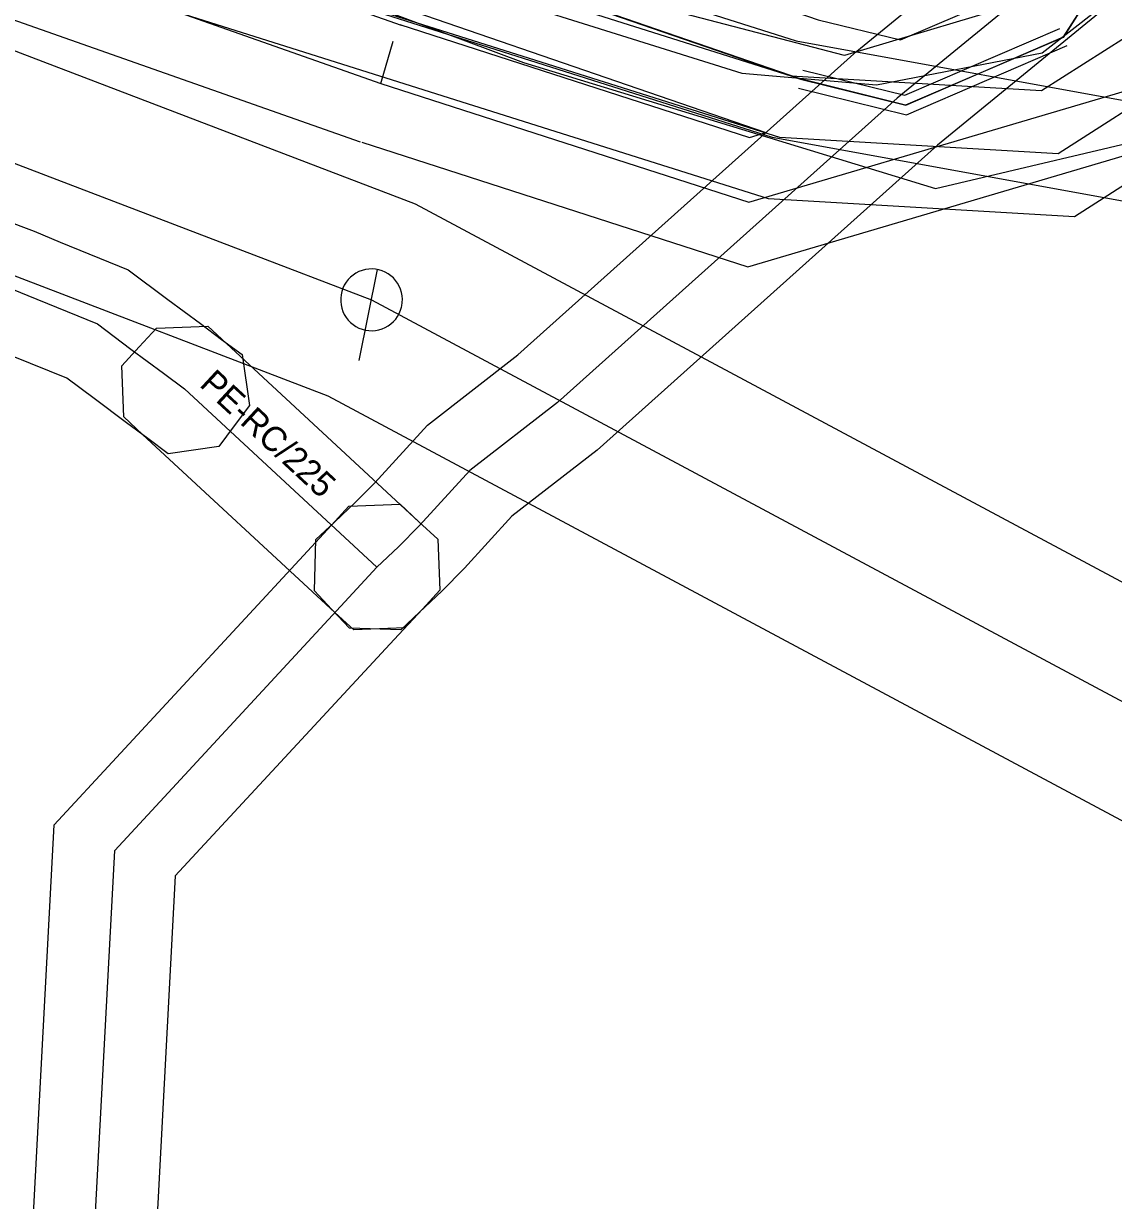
# Model space of a CAD drawing. Extents: x -762993 to -761845, y -975230 to -974501.
# Drawn here: x -762304.94 to -762287.32, y -975003.77 to -974984.74 of the extents above; entities that cross this region are included whole.
import ezdxf

# ---------------------------------------------------------------- set-up
doc = ezdxf.new("R2010")
doc.units = 0
for name, color, linetype in [('IS_CETIN_chranicka', 7, 'Continuous'), ('IS_CETIN_OP', 7, 'Continuous'), ('IS_CETIN_podzem optika zam', 7, 'Continuous'), ('IS_CETIN_podzem out of order', 7, 'Continuous'), ('IS_CEZ-D_OP', 7, 'Continuous'), ('IS_CRA_podzem telekomunikace', 7, 'Continuous'), ('IS_DPmUL_OP', 7, 'Continuous'), ('IS_DPmUL_VO vedeni podzem', 7, 'Continuous'), ('IS_GASNET_plyn NTL anotace', 7, 'Continuous'), ('IS_GASNET_plyn NTL rad', 7, 'Continuous'), ('IS_GASNET_plyn OP', 7, 'Continuous'), ('IS_SCVK_kanalizace jednotna', 7, 'Continuous'), ('IS_SCVK_kanalizace OP', 7, 'Continuous'), ('IS_SCVK_kanalizace znaky', 7, 'Continuous'), ('IS_SCVK_vodovod OP', 7, 'Continuous'), ('IS_SCVK_vodovod privadec', 7, 'Continuous'), ('IS_T-Mobile_OP', 7, 'Continuous')]:
    doc.layers.add(name, color=color, linetype=linetype)

msp = doc.modelspace()

# ---------------------------------------------------------------- linework, layer by layer
at = {"layer": 'IS_CETIN_chranicka'}
for points in [[(-762292.344, -974985.494), (-762290.693, -974985.902), (-762288.189, -974984.822)], [(-762292.416, -974985.786), (-762290.667, -974986.218), (-762288.071, -974985.098)]]:
    msp.add_lwpolyline(points, dxfattribs=at)
at = {"layer": 'IS_CETIN_OP'}
msp.add_line((-762303.634, -974983.077), (-762298.838, -974984.767), dxfattribs=at)
for points in [[(-762332.038, -974969.868), (-762325.973, -974972.002), (-762323.432, -974972.809), (-762321.256, -974973.527), (-762318.954, -974974.571), (-762318.136, -974976.13), (-762306.451, -974980.321), (-762300.467, -974981.8), (-762292.097, -974984.68), (-762290.767, -974985.008), (-762288.807, -974984.163), (-762287.974, -974982.862), (-762287.982, -974982.827), (-762289.282, -974980.773), (-762286.601, -974981.001), (-762284.415, -974982.166)], [(-762325.112, -974977.633), (-762299.502, -974986.653)], [(-762303.634, -974983.077), (-762301.033, -974983.72), (-762292.941, -974986.505)], [(-762298.863, -974984.758), (-762293.207, -974986.583), (-762292.941, -974986.505)], [(-762299.477, -974986.662), (-762293.233, -974988.677), (-762283.623, -974985.836), (-762283.324, -974985.015)]]:
    msp.add_lwpolyline(points, dxfattribs=at)
at = {"layer": 'IS_CETIN_podzem optika zam'}
for points in [[(-762377.62, -974954.57), (-762366.77, -974958.38), (-762363.37, -974959.59), (-762350.74, -974963.98), (-762348.95, -974964.65), (-762339.36, -974968.07), (-762336.01, -974969.53), (-762326.29, -974972.95), (-762323.74, -974973.76), (-762321.62, -974974.46), (-762319.68, -974975.34), (-762318.84, -974976.94), (-762306.74, -974981.28), (-762300.75, -974982.76), (-762292.38, -974985.64), (-762290.68, -974986.06), (-762288.13, -974984.96), (-762286.9, -974983.04), (-762287.05, -974982.43), (-762287.36, -974981.94), (-762286.89, -974981.98), (-762283.27, -974983.91), (-762274.13, -974988.8), (-762260.53, -974993.46)], [(-762299.17, -974985.71), (-762293.22, -974987.63), (-762284.39, -974985.02), (-762281.56, -974977.25), (-762281.87, -974976.53), (-762282.79, -974972.08)], [(-762324.78, -974976.69), (-762299.17, -974985.71)]]:
    msp.add_lwpolyline(points, dxfattribs=at)
at = {"layer": 'IS_CETIN_podzem out of order'}
for points in [[(-762327.23, -974974.06), (-762309.42, -974980.68), (-762296.86, -974985.37), (-762290.2, -974987.41), (-762286.23, -974986.47), (-762283.7, -974985.04), (-762281.71, -974980.9), (-762281.02, -974976.31)], [(-762299.17, -974985.71), (-762298.97, -974985.03)]]:
    msp.add_lwpolyline(points, dxfattribs=at)
at = {"layer": 'IS_CEZ-D_OP'}
msp.add_lwpolyline([(-762305.608, -974981.594), (-762305.175, -974981.831), (-762293.331, -974985.546), (-762291.155, -974985.735), (-762288.473, -974985.215), (-762284.516, -974982.126), (-762283.907, -974980.581), (-762283.529, -974977.898), (-762284.868, -974972.605)], dxfattribs=at)
at = {"layer": 'IS_CRA_podzem telekomunikace'}
msp.add_lwpolyline([(-762286.963, -974982.858), (-762286.915, -974983.05), (-762288.133, -974984.967), (-762290.685, -974986.061), (-762292.389, -974985.635), (-762300.689, -974982.775), (-762306.75, -974981.275), (-762318.851, -974976.949), (-762319.685, -974975.352), (-762321.623, -974974.461), (-762323.743, -974973.764), (-762326.285, -974972.953), (-762335.993, -974969.53), (-762339.363, -974968.07), (-762348.947, -974964.652), (-762363.377, -974959.593), (-762377.637, -974954.573), (-762392.217, -974949.493), (-762417.036, -974940.799), (-762419.044, -974939.84), (-762421.242, -974939.701), (-762425.393, -974938.364)], dxfattribs=at)
at = {"layer": 'IS_DPmUL_OP'}
for points in [[(-762286.443, -974983.158), (-762287.13, -974984.968), (-762288.483, -974985.833), (-762292.533, -974985.594), (-762306.491, -974981.186)], [(-762284.649, -974984.068), (-762285.496, -974986.296), (-762287.953, -974987.867), (-762292.899, -974987.576), (-762307.093, -974983.094)]]:
    msp.add_lwpolyline(points, dxfattribs=at)
at = {"layer": 'IS_DPmUL_VO vedeni podzem'}
msp.add_lwpolyline([(-762285.546, -974983.613), (-762286.313, -974985.632), (-762288.218, -974986.85), (-762292.716, -974986.585), (-762306.792, -974982.14)], dxfattribs=at)
at = {"layer": 'IS_GASNET_plyn NTL rad'}
for points in [[(-762416.145, -974949.855), (-762381.041, -974961.735), (-762378.19, -974962.7), (-762377.47, -974962.93), (-762377.29, -974962.99), (-762377.092, -974963.051), (-762377.03, -974963.07), (-762356.37, -974970.3), (-762354.158, -974971.062), (-762353.96, -974971.13), (-762350.61, -974972.23), (-762350.171, -974972.416), (-762350.02, -974972.48), (-762336.17, -974977.35), (-762335.29, -974977.64), (-762335.11, -974977.68), (-762305.627, -974988.849), (-762305.14, -974989.03), (-762304.73, -974989.2), (-762303.75, -974989.6), (-762303.207, -974990.005), (-762302.681, -974990.396), (-762302.34, -974990.65)], [(-762268.53, -974977.47), (-762279.25, -974979.81), (-762282.69, -974980.71), (-762285.02, -974981.56), (-762287.51, -974983.24), (-762290.82, -974985.95), (-762296.31, -974990.87), (-762297.73, -974991.97), (-762298.54, -974992.86), (-762298.88, -974993.2), (-762299.23, -974993.53)], [(-762302.34, -974990.65), (-762299.23, -974993.53)], [(-762382.14, -975056.56), (-762374.12, -975052.41), (-762369.1, -975049.66), (-762366.32, -975048.11), (-762358.1, -975043.65), (-762340.31, -975033.92), (-762334.72, -975030.54), (-762325.49, -975025.85), (-762316.08, -975020.74), (-762311.6, -975018.18), (-762307.32, -975015.61), (-762304.68, -975013.94), (-762304.65, -975013.71), (-762304.31, -975011.18), (-762303.9, -975006.19), (-762303.47, -974998.11), (-762299.684, -974994.021), (-762299.23, -974993.53)]]:
    msp.add_lwpolyline(points, dxfattribs=at)
at = {"layer": 'IS_GASNET_plyn OP'}
for points in [[(-762334.823, -974976.719), (-762305.276, -974987.913), (-762304.774, -974988.099), (-762304.35, -974988.275), (-762303.254, -974988.722), (-762302.61, -974989.203), (-762302.084, -974989.594), (-762301.743, -974989.848), (-762301.411, -974990.095), (-762301.291, -974990.915), (-762301.538, -974991.247), (-762301.785, -974991.579), (-762302.605, -974991.699), (-762302.937, -974991.452), (-762303.278, -974991.198), (-762303.804, -974990.807), (-762304.246, -974990.478), (-762305.11, -974990.125), (-762305.506, -974989.961), (-762305.978, -974989.785), (-762335.397, -974978.641)], [(-762286.912, -974984.043), (-762290.169, -974986.71), (-762295.669, -974991.639), (-762297.049, -974992.707), (-762297.816, -974993.55), (-762298.183, -974993.918), (-762298.544, -974994.258), (-762298.846, -974994.542), (-762299.674, -974994.518), (-762299.958, -974994.216), (-762300.242, -974993.914), (-762300.218, -974993.086), (-762299.916, -974992.802), (-762299.577, -974992.482), (-762299.264, -974992.17), (-762298.411, -974991.233), (-762296.951, -974990.101), (-762291.471, -974985.19), (-762288.108, -974982.437)], [(-762304.898, -975006.122), (-762304.449, -974997.696), (-762300.418, -974993.342), (-762299.964, -974992.851), (-762299.683, -974992.547), (-762298.855, -974992.515), (-762298.551, -974992.796), (-762298.247, -974993.077), (-762298.215, -974993.905), (-762298.496, -974994.209), (-762298.95, -974994.7), (-762302.491, -974998.524), (-762302.902, -975006.258)]]:
    msp.add_lwpolyline(points, dxfattribs=at)
msp.add_lwpolyline([(-762301.965, -974989.635), (-762301.661, -974989.916), (-762298.551, -974992.796), (-762298.247, -974993.078), (-762298.215, -974993.905), (-762298.496, -974994.209), (-762298.778, -974994.513), (-762299.605, -974994.545), (-762299.909, -974994.264), (-762303.019, -974991.384), (-762303.323, -974991.102), (-762303.355, -974990.275), (-762303.074, -974989.971), (-762302.792, -974989.667)], close=True, dxfattribs=at)
at = {"layer": 'IS_SCVK_kanalizace jednotna'}
for points in [[(-762330.791, -974977.171), (-762299.318, -974989.209)], [(-762299.318, -974989.209), (-762270.284, -975004.741)]]:
    msp.add_lwpolyline(points, dxfattribs=at)
at = {"layer": 'IS_SCVK_kanalizace OP'}
for p, q in [((-762330.184, -974975.583), (-762298.611, -974987.659)), ((-762331.398, -974978.759), (-762300.025, -974990.759)), ((-762298.611, -974987.659), (-762269.759, -975003.094)), ((-762300.025, -974990.759), (-762270.809, -975006.388))]:
    msp.add_line(p, q, dxfattribs=at)
at = {"layer": 'IS_SCVK_kanalizace znaky'}
for points in [[(-762298.828, -974989.309), (-762298.82, -974989.254), (-762298.818, -974989.2), (-762298.822, -974989.145), (-762298.832, -974989.091), (-762298.848, -974989.039), (-762298.869, -974988.988), (-762298.896, -974988.941), (-762298.928, -974988.896), (-762298.965, -974988.855), (-762299.005, -974988.819), (-762299.05, -974988.787), (-762299.098, -974988.76), (-762299.148, -974988.739), (-762299.201, -974988.723), (-762299.255, -974988.713), (-762299.309, -974988.709), (-762299.364, -974988.711), (-762299.418, -974988.719), (-762299.471, -974988.733), (-762299.522, -974988.753), (-762299.571, -974988.778), (-762299.616, -974988.808), (-762299.659, -974988.843), (-762299.697, -974988.883), (-762299.73, -974988.926), (-762299.758, -974988.973), (-762299.782, -974989.022), (-762299.799, -974989.074), (-762299.811, -974989.128), (-762299.817, -974989.182), (-762299.817, -974989.236), (-762299.811, -974989.291), (-762299.799, -974989.344), (-762299.782, -974989.396), (-762299.758, -974989.446), (-762299.73, -974989.493), (-762299.696, -974989.536), (-762299.659, -974989.575), (-762299.617, -974989.61), (-762299.571, -974989.641), (-762299.522, -974989.666), (-762299.471, -974989.685), (-762299.417, -974989.699), (-762299.364, -974989.707), (-762299.309, -974989.709), (-762299.255, -974989.705), (-762299.201, -974989.695), (-762299.148, -974989.679), (-762299.098, -974989.658), (-762299.05, -974989.631), (-762299.005, -974989.6), (-762298.965, -974989.562), (-762298.927, -974989.522), (-762298.896, -974989.478), (-762298.869, -974989.43), (-762298.848, -974989.379), (-762298.832, -974989.327), (-762298.828, -974989.309)], [(-762299.517, -974990.189), (-762299.219, -974988.719)]]:
    msp.add_lwpolyline(points, dxfattribs=at)
at = {"layer": 'IS_SCVK_vodovod OP'}
msp.add_lwpolyline([(-762371.852, -974959.319), (-762366.733, -974961.125), (-762365.959, -974961.392), (-762351.074, -974966.651), (-762348.097, -974967.643), (-762328.082, -974974.681), (-762324.702, -974975.757), (-762322.277, -974976.604), (-762303.577, -974983.171), (-762292.841, -974986.577), (-762286.645, -974987.706), (-762284.209, -974987.979), (-762282.49, -974987.47)], dxfattribs=at)
at = {"layer": 'IS_SCVK_vodovod privadec'}
msp.add_lwpolyline([(-762371.32, -974957.81), (-762366.206, -974959.614), (-762365.432, -974959.881), (-762350.555, -974965.138), (-762347.579, -974966.129), (-762327.574, -974973.164), (-762324.195, -974974.239), (-762321.748, -974975.094), (-762303.07, -974981.653), (-762292.454, -974985.021), (-762286.412, -974986.122), (-762284.353, -974986.353), (-762281.669, -974985.558)], dxfattribs=at)
at = {"layer": 'IS_T-Mobile_OP'}
for p, q in [((-762287.693, -974984.069), (-762291.671, -974985.258)), ((-762291.671, -974985.258), (-762294.627, -974984.487))]:
    msp.add_line(p, q, dxfattribs=at)

# ---------------------------------------------------------------- texts
at = {"layer": 'IS_GASNET_plyn NTL anotace'}
msp.add_text('PE-RC/225', height=0.4, rotation=317.1989, dxfattribs=at).set_placement((-762302.116, -974990.597))

doc.saveas('drawing.dxf')
